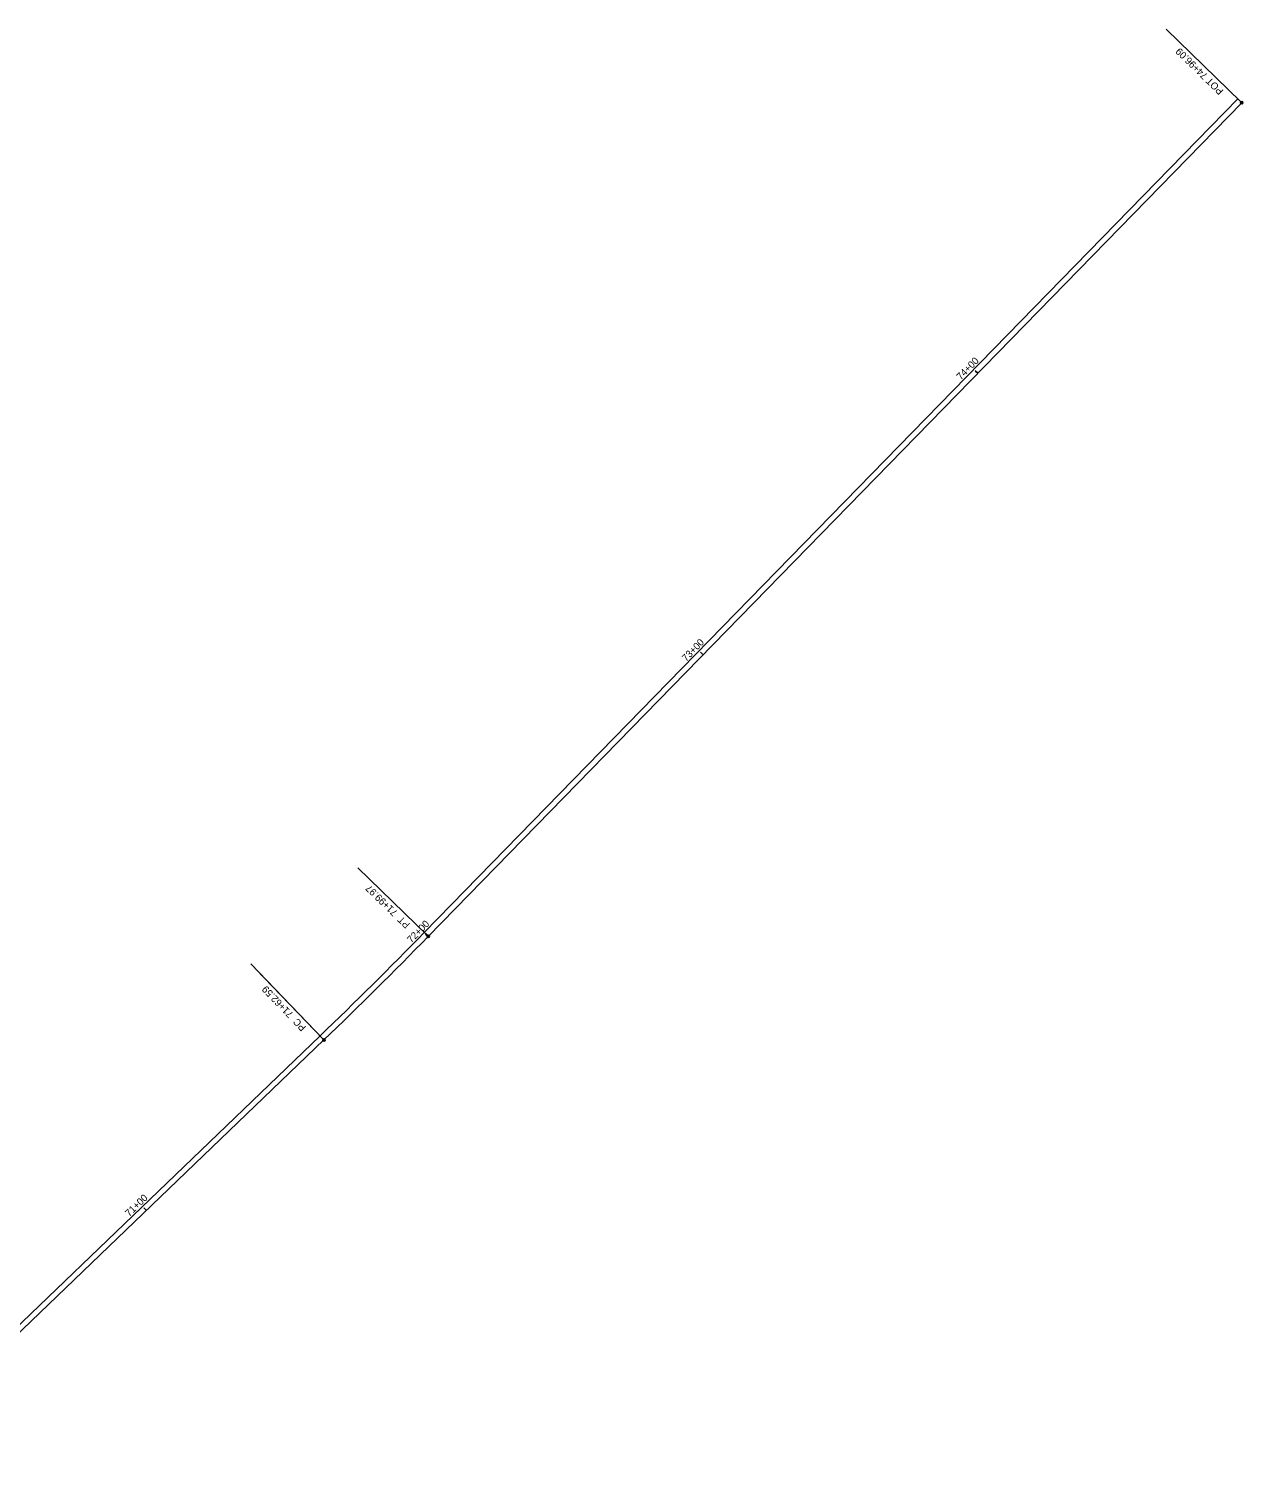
# Model space of a CAD drawing. Extents: x 2255019 to 2255637, y 13790912 to 13791457.
# Drawn here: x 2255328 to 2255636.6, y 13791087.6 to 13791457.1 of the extents above; entities that cross this region are included whole.
import ezdxf

# ---------------------------------------------------------------- set-up
doc = ezdxf.new("R2010")
doc.units = 0
for name, color, linetype in [('D_ALIGN_ANNO_1', 7, 'Continuous'), ('D_ALIGN_ANNO_2', 7, 'Continuous'), ('Struc_Wall', 7, 'Continuous')]:
    doc.layers.add(name, color=color, linetype=linetype)

msp = doc.modelspace()

# ---------------------------------------------------------------- linework, layer by layer
at = {"layer": 'D_ALIGN_ANNO_1'}
for p, q in [((2255636.13, 13791438.63), (2255617.15, 13791457.15)), ((2255569.23, 13791369.65), (2255568.59, 13791370.28)), ((2255499.39, 13791298.09), (2255498.75, 13791298.71)), ((2255429.55, 13791226.52), (2255428.9, 13791227.14)), ((2255402.79, 13791200.39), (2255384.43, 13791219.51)), ((2255357.85, 13791156.82), (2255357.22, 13791157.47))]:
    msp.add_line(p, q, dxfattribs=at)
for centre in [(2255636.34, 13791438.43), (2255429.52, 13791226.49), (2255402.99, 13791200.17)]:
    msp.add_circle(centre, 0.3, dxfattribs=at)
at = {"layer": 'D_ALIGN_ANNO_2'}
for p, q in [((2255429.31, 13791226.7), (2255411.65, 13791243.94)), ((2255429.49, 13791226.46), (2255428.85, 13791227.08)), ((2255402.79, 13791200.39), (2255385.69, 13791218.19))]:
    msp.add_line(p, q, dxfattribs=at)
for centre in [(2255429.52, 13791226.49), (2255402.99, 13791200.17)]:
    msp.add_circle(centre, 0.3, dxfattribs=at)
at = {"layer": 'Struc_Wall'}
for p, q in [((2255428.48, 13791227.45), (2255635.33, 13791439.41)), ((2255429.49, 13791226.46), (2255636.34, 13791438.43)), ((2255635.33, 13791439.41), (2255636.34, 13791438.43)), ((2255284.74, 13791088.57), (2255402.01, 13791201.19)), ((2255285.72, 13791087.55), (2255402.99, 13791200.17))]:
    msp.add_line(p, q, dxfattribs=at)
for radius in [1150.08, 1151.5]:
    msp.add_arc((2254605.4, 13792030.71), radius, 313.84074, 315.69794, dxfattribs=at)

# ---------------------------------------------------------------- texts
at = {"layer": 'D_ALIGN_ANNO_1'}
for s, rotation, p in [('POT 74+96.09', 135.7003, (2255631.85, 13791441.55)), ('74+00', 45.7003, (2255564.93, 13791367.82)), ('73+00', 45.7003, (2255495.09, 13791296.25)), ('PT  71+99.97', 135.6538, (2255425.03, 13791229.62)), ('72+00', 45.7003, (2255425.25, 13791224.68)), ('PC  71+62.59', 133.8407, (2255398.6, 13791203.44)), ('71+00', 43.8407, (2255353.49, 13791155.13))]:
    msp.add_text(s, height=1.8, rotation=rotation, dxfattribs=at).set_placement(p)

doc.saveas('drawing.dxf')
